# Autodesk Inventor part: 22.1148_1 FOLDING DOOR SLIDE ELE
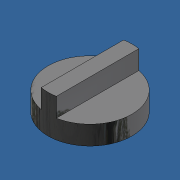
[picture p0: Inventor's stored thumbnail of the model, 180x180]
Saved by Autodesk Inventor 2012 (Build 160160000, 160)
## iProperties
Created: 2014-04
Part Number: 22.1148_1 FOLDING DOOR SLIDE ELE
Material: UHMW, Black
Document SubType Name: Modeling
Designer: Admin
Mass: 28.8464 g
Surface Area: 58.4594 cm^2
Volume: 30.6877 cm^3
Density: 0.94 g/cm^3
Author: Admin
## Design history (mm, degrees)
sketch "Sketch1"
  geometry: C1 r 22.1 at (0, 0); 1 further point
  constraints: 1 centre point, 1 coincident
  dimensions: "d0" = 44.2 diameter of C1
extrude "Extrusion1" new body sketch "Sketch1" distance "d1" = 20; taper "d2" = 0 deg
sketch "Sketch2"
  geometry: L1 (-22.1, -31.855)-(-4, -31.855); L2 (-4, -31.855)-(-4, 30.052); L3 (-4, 30.052)-(-22.1, 30.052); L4 (-22.1, 30.052)-(-22.1, -31.855); L5 (22.1, -28.674)-(4, -28.674); L6 (4, -28.674)-(4, 31.855); L7 (4, 31.855)-(22.1, 31.855); L8 (22.1, 31.855)-(22.1, -28.674); C1 r 22.1 at (0, 0) reference
  constraints: 16 end point, 5 parallel, 2 horizontal, 2 perpendicular, 2 tangent
  dimensions: "d3" = 8 distance between parallel lines of L6 L2
extrude "Extrusion2" cut sketch "Sketch2" distance "d4" = 10; taper "d5" = 0 deg
sketch "Sketch3"
  geometry: C1 r 22.1 at (0, 0) reference; C2 r 6.75 at (0, 0)
  constraints: 1 centre point, 1 coincident
  dimensions: "d6" = 13.5 diameter of C2
extrude "Extrusion3" cut sketch "Sketch3" distance "d7" = 8; taper "d8" = 0 deg
body "Solid1"
